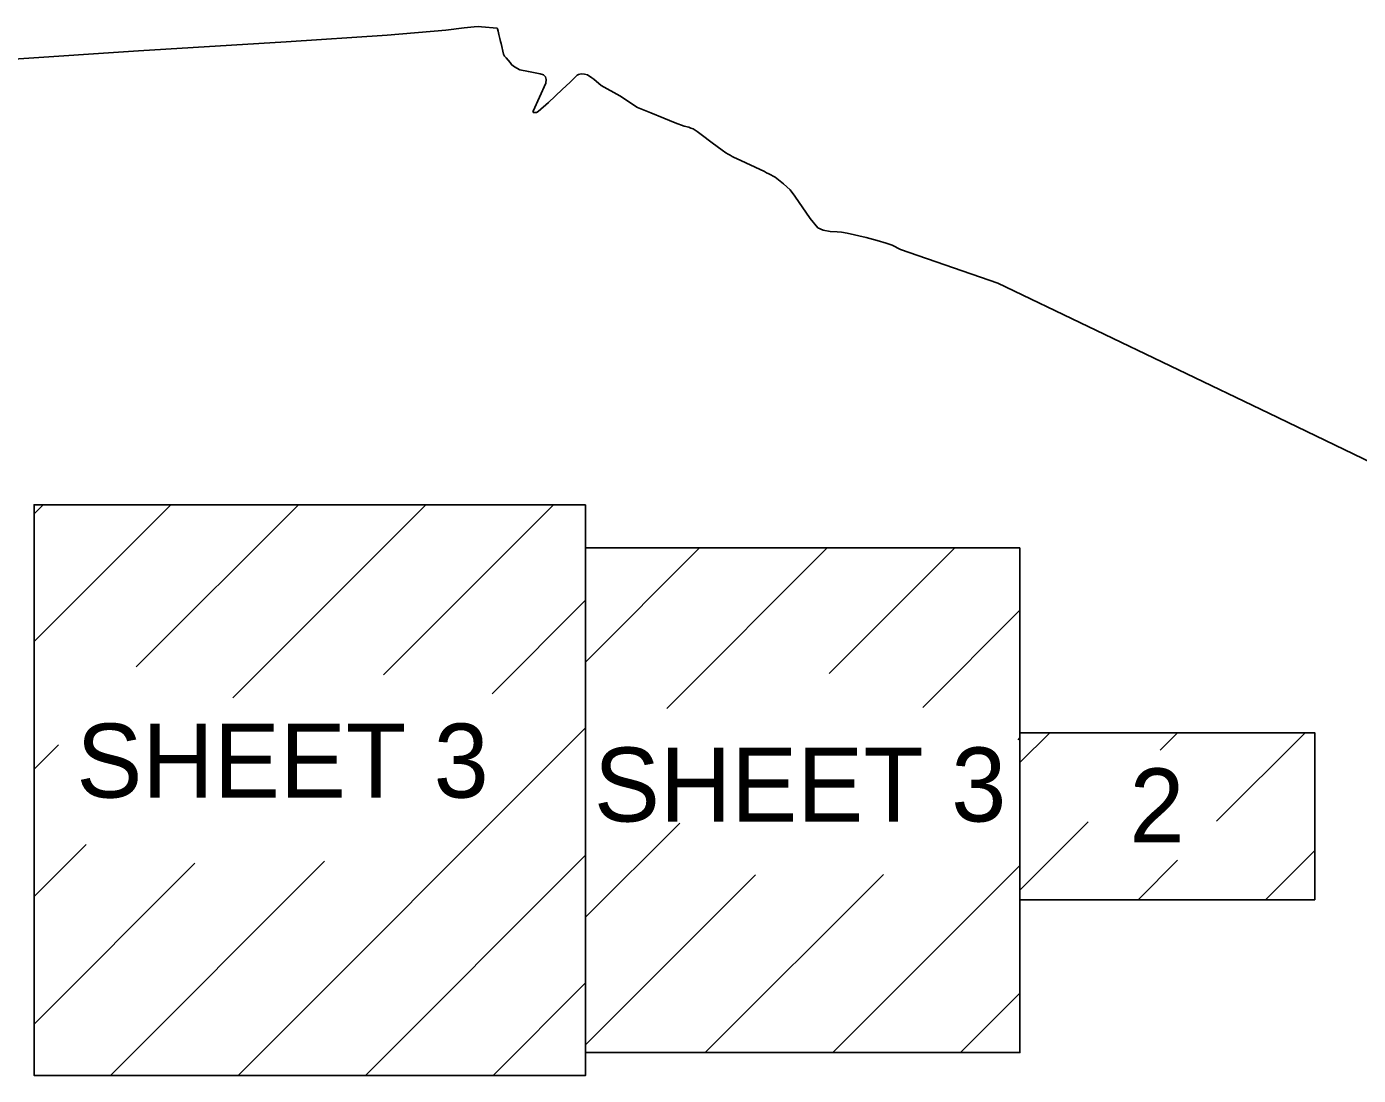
# Model space of a CAD drawing. Extents: x 5197761 to 5514561, y 1890130 to 2080942.
# Drawn here: x 5439404 to 5454166, y 1948499 to 1960124 of the extents above; entities that cross this region are included whole.
import ezdxf

# ---------------------------------------------------------------- set-up
doc = ezdxf.new("R2010")
doc.units = 0
doc.layers.add('Map Preparation Base Sheet Key Label', color=7, linetype='Continuous')
doc.layers.add('Map Preparation Base Sheet Key Shape', color=7, linetype='Continuous')

msp = doc.modelspace()

# ---------------------------------------------------------------- linework, layer by layer
at = {"layer": 'Map Preparation Base Sheet Key Shape'}
for p, q in [((5439486, 1954723), (5439588, 1954825)), ((5439486, 1953308), (5441002, 1954825)), ((5440618, 1953026), (5442416, 1954825)), ((5441690, 1952684), (5443830, 1954825)), ((5443359, 1952939), (5445245, 1954825)), ((5445600, 1953081), (5446864, 1954345)), ((5446500, 1952566), (5448278, 1954345)), ((5448301, 1952954), (5449692, 1954345)), ((5444563, 1952729), (5445600, 1953766)), ((5449340, 1952578), (5450415, 1953654)), ((5441748, 1948499), (5445600, 1952352)), ((5450395, 1952219), (5450415, 1952240)), ((5450415, 1951966), (5450747, 1952297)), ((5451968, 1952105), (5452161, 1952297)), ((5452593, 1951315), (5453575, 1952297)), ((5439486, 1951894), (5439756, 1952164)), ((5445600, 1950253), (5446643, 1951296)), ((5450415, 1950552), (5451173, 1951309)), ((5439486, 1950480), (5440065, 1951059)), ((5443162, 1948499), (5445600, 1950938)), ((5453138, 1950446), (5453683, 1950991)), ((5439486, 1949066), (5441270, 1950850)), ((5440333, 1948499), (5442706, 1950872)), ((5448341, 1948751), (5450415, 1950825)), ((5451724, 1950446), (5452162, 1950884)), ((5445600, 1948839), (5447483, 1950721)), ((5446927, 1948751), (5448903, 1950727)), ((5444576, 1948499), (5445600, 1949523)), ((5449755, 1948751), (5450415, 1949411))]:
    msp.add_line(p, q, dxfattribs=at)
for points in [[(5439263, 1959762), (5440644, 1959854), (5442279, 1959957), (5443402, 1960030), (5444052, 1960085), (5444253, 1960109), (5444364, 1960121), (5444409, 1960124), (5444446, 1960123), (5444619, 1960106), (5444624, 1960101), (5444630, 1960074), (5444640, 1960037), (5444649, 1959991), (5444656, 1959958), (5444663, 1959937), (5444690, 1959819), (5444701, 1959796), (5444720, 1959777)], [(5444720, 1959777), (5444764, 1959727), (5444779, 1959704), (5444799, 1959686), (5444836, 1959665), (5444871, 1959646), (5444967, 1959625), (5445096, 1959600), (5445133, 1959588), (5445146, 1959579), (5445157, 1959566), (5445162, 1959537), (5445161, 1959498), (5445020, 1959188), (5445015, 1959178), (5445021, 1959172), (5445035, 1959171), (5445056, 1959172), (5445074, 1959185), (5445189, 1959282), (5445342, 1959428), (5445428, 1959508), (5445477, 1959555), (5445507, 1959586), (5445521, 1959594), (5445552, 1959599), (5445588, 1959596), (5445621, 1959589), (5445671, 1959557), (5445693, 1959542), (5445773, 1959473), (5445979, 1959356), (5446175, 1959228), (5446323, 1959170), (5446469, 1959108), (5446592, 1959059), (5446691, 1959022), (5446743, 1959008), (5446768, 1959000), (5446792, 1958990), (5446816, 1958978), (5446838, 1958963), (5446880, 1958930), (5447004, 1958835), (5447113, 1958756), (5447156, 1958726), (5447179, 1958712), (5447201, 1958698), (5447224, 1958685), (5447248, 1958673), (5447272, 1958661), (5447584, 1958518), (5447607, 1958505), (5447630, 1958491), (5447702, 1958457), (5447794, 1958382), (5447867, 1958314), (5447918, 1958244), (5448089, 1957996), (5448175, 1957895), (5448232, 1957869), (5448312, 1957854), (5448388, 1957851), (5448438, 1957845), (5448500, 1957834), (5448712, 1957786), (5448834, 1957755), (5448932, 1957724), (5448998, 1957702), (5449092, 1957655), (5450170, 1957282), (5453174, 1955839), (5455366, 1954782)]]:
    msp.add_lwpolyline(points, dxfattribs=at)
for points in [[(5445600, 1954825), (5439486, 1954825), (5439486, 1948499), (5445600, 1948499)], [(5450415, 1954345), (5445600, 1954345), (5445600, 1948751), (5450415, 1948751)], [(5450415, 1950446), (5453683, 1950446), (5453683, 1952297), (5450415, 1952297)]]:
    msp.add_lwpolyline(points, close=True, dxfattribs=at)

# ---------------------------------------------------------------- texts
at = {"layer": 'Map Preparation Base Sheet Key Label'}
for s, height, p in [('SHEET 3', 820.2, (5439955, 1951578)), ('SHEET 3', 820.2, (5445692, 1951313)), ('2', 820, (5451629, 1951081))]:
    msp.add_text(s, height=height, dxfattribs=at).set_placement(p)

doc.saveas('drawing.dxf')
